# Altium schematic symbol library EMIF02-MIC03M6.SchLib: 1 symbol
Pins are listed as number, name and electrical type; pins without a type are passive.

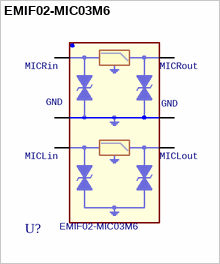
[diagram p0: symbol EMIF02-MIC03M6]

## EMIF02-MIC03M6
designator U?
footprint ST_QFN50P145X100X55-6L
pins: 1 MICRin, 2 GND, 3 MICLin, 4 MICLout, 5 GND1, 6 MICRout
